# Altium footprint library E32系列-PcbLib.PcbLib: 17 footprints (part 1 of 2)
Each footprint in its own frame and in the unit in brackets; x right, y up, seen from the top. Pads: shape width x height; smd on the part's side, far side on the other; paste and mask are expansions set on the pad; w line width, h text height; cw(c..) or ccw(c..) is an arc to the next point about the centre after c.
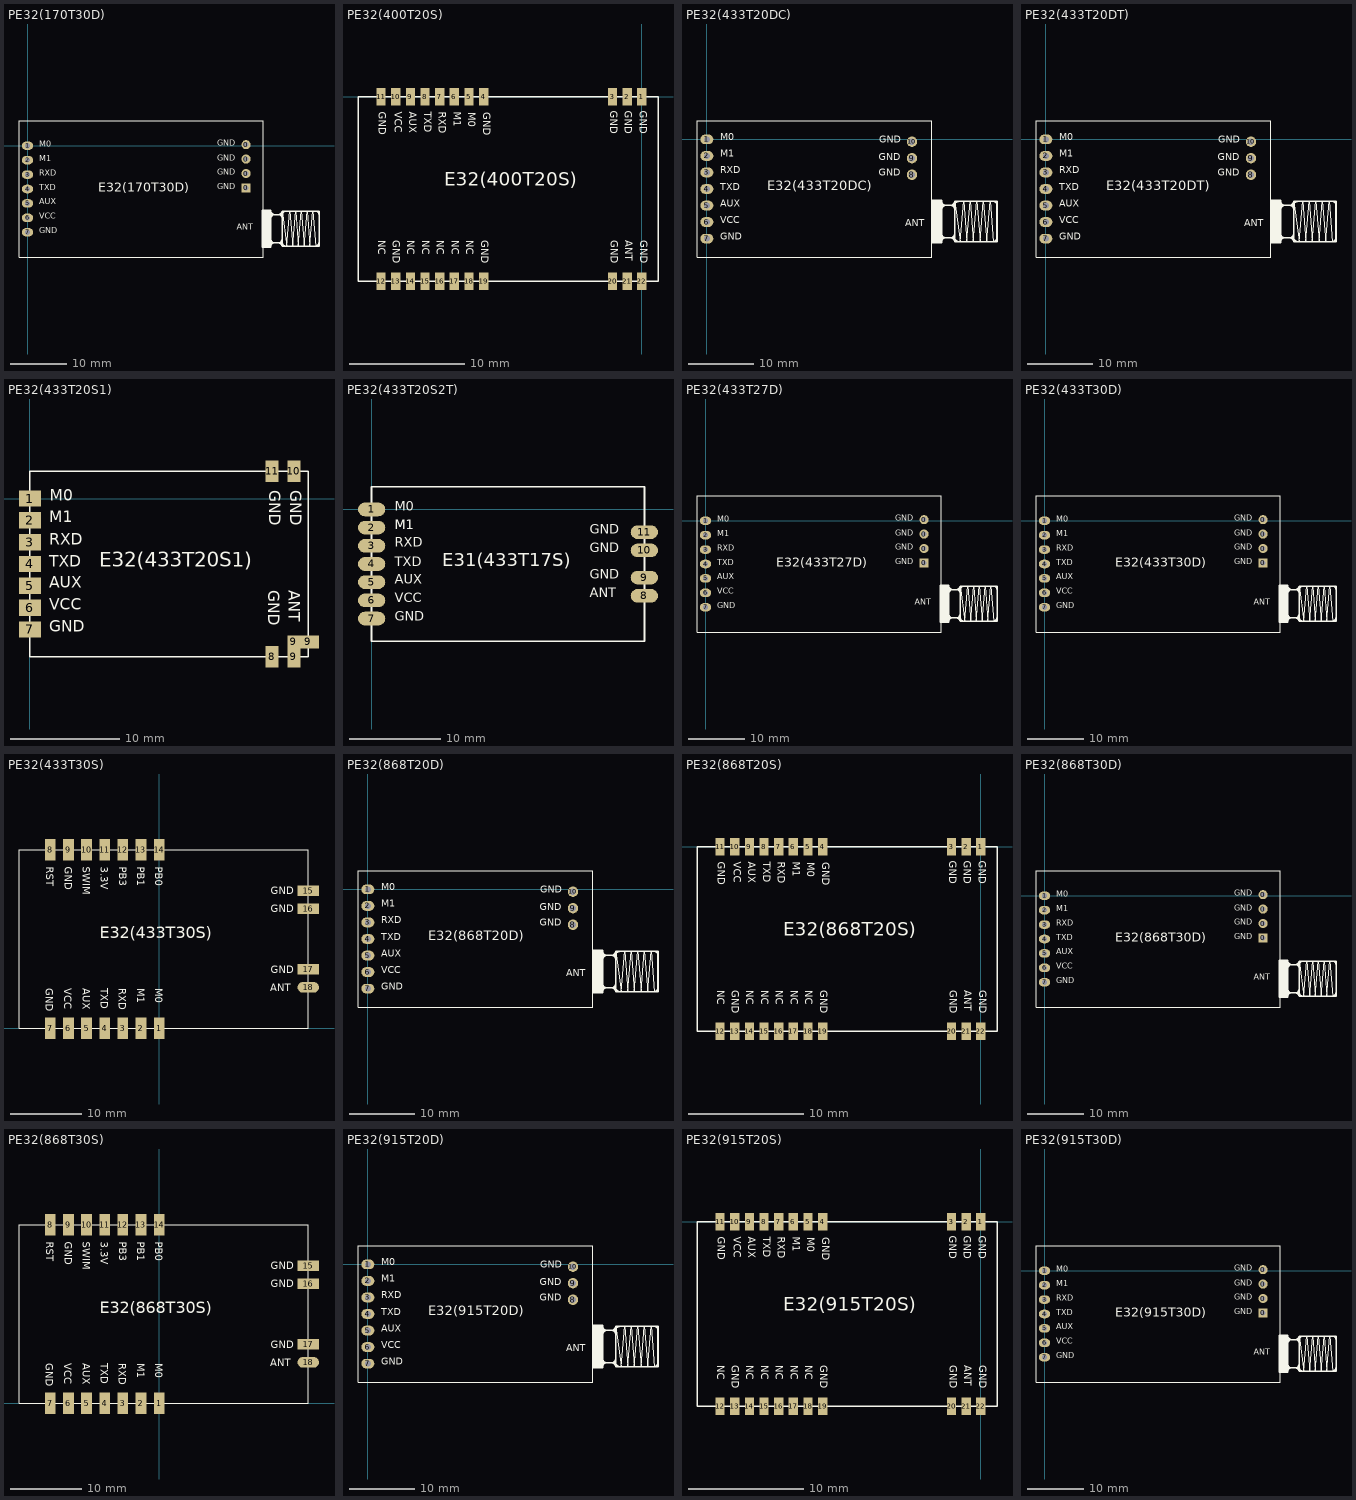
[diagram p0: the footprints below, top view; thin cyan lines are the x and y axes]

## PE32(170T30D) [mm] "43MM*24mm-D//SMA长度12.5mm"
pads (11):
  rect 1.6x1.6 hole 0.9: 0(38.5,-7.43)
  round 1.6 hole 0.9: 0(38.5,-4.89) 0(38.5,-2.35) 0(38.5,0.19)
  oval 2x1.5 hole 0.9: 1(0,0) 2(0,-2.54) 3(0,-5.08) 4(0,-7.62) 5(0,-10.16) 6(0,-12.7) 7(0,-15.24)
Top Overlay:
  rectangle: 41.35,-17.87 42.85,-11.37
  rectangle: 41.35,-17.865 42.85,-11.365
  lines w0.1: 45.7,-17.72 46.22,-11.52 ; 45.7,-17.72 44.85,-11.52 45.7,-17.72 ; 45.7,-17.72 46.22,-11.52 ; 46.22,-11.52 46.73,-17.72 ; 46.22,-11.52 46.73,-17.72 ; 46.73,-17.72 47.24,-11.52 ; 46.73,-17.72 47.24,-11.52 ; 47.24,-11.52 47.72,-17.72 ; 47.24,-11.52 47.72,-17.72 ; 47.72,-17.72 48.24,-11.52 ; 47.72,-17.72 48.24,-11.52 ; 48.24,-11.52 48.75,-17.72 ; 48.24,-11.52 48.75,-17.72 ; 48.75,-17.72 49.24,-11.52 ; 48.75,-17.72 49.24,-11.52 ; 49.24,-11.52 49.76,-17.72 ; 49.24,-11.52 49.76,-17.72 ; 49.76,-17.72 50.28,-11.52 ; 49.76,-17.72 50.28,-11.52 ; 50.28,-11.52 50.79,-17.72 50.28,-11.52 ; -1.5,-19.62 41.5,-19.62 41.5,4.38 -1.5,4.38 -1.5,-19.62
  lines w0.254: 41.35,-17.87 42.85,-17.87 ; 41.35,-17.87 41.35,-11.37 ; 41.35,-17.87 42.85,-17.87 ; 41.35,-17.87 41.35,-11.37 ; 41.35,-11.37 42.85,-11.37 ; 41.35,-11.37 42.85,-11.37 ; 42.85,-17.87 42.85,-11.37 ; 42.85,-17.87 42.85,-11.37 ; 42.85,-16.47 ccw(c43.5,-16.47) 43.5,-17.12 ; 42.85,-16.47 ccw(c43.5,-16.47) 43.5,-17.12 ; 42.85,-16.47 42.85,-16.1 42.85,-16.47 ; 42.85,-12.82 cw(c43.55,-12.82) 43.55,-12.12 ; 42.85,-12.82 cw(c43.55,-12.82) 43.55,-12.12 ; 42.85,-12.82 42.85,-13.74 42.85,-12.82 ; 42.85,-11.49 ccw(c43.48,-11.49) 43.48,-12.12 ; 42.85,-11.49 ccw(c43.48,-11.49) 43.48,-12.12 ; 42.85,-11.49 42.85,-11.37 ; 42.85,-11.49 42.85,-11.37 ; 43.4,-17.12 ccw(c43.4,-17.67) 42.85,-17.67 cw(c43.4,-17.67) 43.4,-17.12 ; 43.4,-17.12 44.25,-17.12 ; 43.4,-17.12 44.25,-17.12 ; 43.48,-12.12 44.25,-12.12 ; 43.48,-12.12 44.25,-12.12 ; 43.5,-17.12 44.22,-17.12 ; 43.5,-17.12 44.22,-17.12 ; 43.55,-12.12 44.25,-12.12 ; 43.55,-12.12 44.25,-12.12 ; 44.22,-17.12 ccw(c44.22,-16.49) 44.85,-16.49 cw(c44.22,-16.49) 44.22,-17.12 ; 44.25,-17.12 cw(c44.25,-17.72) 44.85,-17.72 ; 44.25,-17.12 cw(c44.25,-17.72) 44.85,-17.72 ; 44.25,-12.12 cw(c44.25,-12.72) 44.85,-12.72 ccw(c44.25,-12.72) 44.25,-12.12 ; 44.25,-12.12 ccw(c44.25,-11.52) 44.85,-11.52 ; 44.25,-12.12 ccw(c44.25,-11.52) 44.85,-11.52 ; 44.85,-17.72 44.85,-11.52 ; 44.85,-17.72 51.35,-17.72 ; 44.85,-17.72 44.85,-11.52 ; 44.85,-17.72 51.35,-17.72 ; 44.85,-11.52 51.35,-11.52 ; 44.85,-11.52 51.35,-11.52 ; 45.53,-17.72 cw(c45.53,-17.04) 44.85,-17.04 ccw(c45.53,-17.04) 45.53,-17.72 ; 45.53,-17.72 45.68,-17.72 45.53,-17.72 ; 50.73,-17.72 ccw(c50.73,-17.1) 51.35,-17.1 cw(c50.73,-17.1) 50.73,-17.72 ; 50.73,-17.72 50.5,-17.72 50.73,-17.72 ; 50.81,-11.52 cw(c50.81,-12.06) 51.35,-12.06 ccw(c50.81,-12.06) 50.81,-11.52 ; 50.81,-11.52 50.41,-11.52 50.81,-11.52 ; 51.35,-17.72 51.35,-11.52 ; 51.35,-17.72 51.35,-11.52 ; 42.68,-17.12 44.85,-17.12 42.68,-17.12 ; 42.85,-12.12 44.85,-12.12 42.85,-12.12 ; 44.85,-12.13 cw(c45.46,-12.13) 45.46,-11.52 ccw(c45.46,-12.13) 44.85,-12.13
  text "E32(170T30D)" at 12.446,-8.763 h2.8
  text "ANT" at 36.83,-15.19 h1.8
  text "M0" at 2.063,-0.54 h1.8
  text "M1" at 2.063,-3.08 h1.8
  text "RXD" at 2.063,-5.62 h1.8
  text "TXD" at 2.063,-8.16 h1.8
  text "AUX" at 2.063,-10.7 h1.8
  text "VCC" at 2.063,-13.24 h1.8
  text "GND" at 2.063,-15.78 h1.8
  text "GND" at 33.426,-5.429 h1.8
  text "GND" at 33.426,-3.016 h1.8
  text "GND" at 33.457,-0.381 h1.8
  text "GND" at 33.457,-8.001 h1.8

## PE32(400T20S) [mm] "26mm**16mm*3.23mm-S"
pads (22):
  rect 0.8x1.5 smd: 1(0,0) 2(-1.27,0) 3(-2.54,0) 4(-13.71,0) 5(-14.98,0) 6(-16.25,0) 7(-17.52,0) 8(-18.79,0) 9(-20.06,0) 10(-21.33,0) 11(-22.6,0) 12(-22.6,-16) 13(-21.33,-16) 14(-20.06,-16) 15(-18.79,-16) 16(-17.52,-16) 17(-16.25,-16) 18(-14.98,-16) 19(-13.71,-16) 20(-2.54,-16) 21(-1.27,-16) 22(0,-16)
Top Overlay:
  lines w0.127: -24.6,-16 1.4,-16 1.4,0 -24.6,0 -24.6,-16
  text "GND" at -1.687,-1.224 h1.1
  text "GND" at -2.966,-1.224 h1.1
  text "GND" at -2.916,-12.441 h1.1
  text "ANT" at -1.637,-12.441 h1.1
  text "GND" at -0.358,-12.441 h1.1
  text "GND" at -14.138,-12.441 h1.1
  text "NC" at -15.417,-12.441 h1.1
  text "NC" at -16.696,-12.441 h1.1
  text "NC" at -17.974,-12.441 h1.1
  text "NC" at -19.253,-12.441 h1.1
  text "NC" at -20.532,-12.441 h1.1
  text "GND" at -21.811,-12.441 h1.1
  text "NC" at -23.06,-12.441 h1.1
  text "GND" at -13.97,-1.351 h1.1
  text "GND" at -23.01,-1.301 h1.1
  text "VCC" at -21.651,-1.301 h1.1
  text "AUX" at -20.372,-1.301 h1.1
  text "TXD" at -19.093,-1.301 h1.1
  text "RXD" at -17.814,-1.301 h1.1
  text "M1" at -16.536,-1.301 h1.1
  text "M0" at -15.257,-1.351 h1.1
  text "E32(400T20S)" at -17.107,-8.126 h2
  text "GND" at -0.408,-1.224 h1.1

## PE32(433T20DC) [mm] "36mm*21mm-D/SMA长度12.5mm"
pads (10):
  oval 2x1.5 hole 0.9: 1(0,0) 2(0,-2.54) 3(0,-5.08) 4(0,-7.62) 5(0,-10.16) 6(0,-12.7) 7(0,-15.24)
  round 1.6 hole 1: 8(31.49,-5.43) 9(31.49,-2.89) 10(31.49,-0.35)
Top Overlay:
  rectangle: 34.54,-15.87 36.04,-9.37
  rectangle: 34.54,-15.865 36.04,-9.365
  lines w0.1: 38.89,-15.72 39.41,-9.52 ; 38.89,-15.72 38.04,-9.52 38.89,-15.72 ; 38.89,-15.72 39.41,-9.52 ; 39.41,-9.52 39.92,-15.72 ; 39.41,-9.52 39.92,-15.72 ; 39.92,-15.72 40.43,-9.52 ; 39.92,-15.72 40.43,-9.52 ; 40.43,-9.52 40.91,-15.72 ; 40.43,-9.52 40.91,-15.72 ; 40.91,-15.72 41.43,-9.52 ; 40.91,-15.72 41.43,-9.52 ; 41.43,-9.52 41.94,-15.72 ; 41.43,-9.52 41.94,-15.72 ; 41.94,-15.72 42.43,-9.52 ; 41.94,-15.72 42.43,-9.52 ; 42.43,-9.52 42.95,-15.72 ; 42.43,-9.52 42.95,-15.72 ; 42.95,-15.72 43.47,-9.52 ; 42.95,-15.72 43.47,-9.52 ; 43.47,-9.52 43.98,-15.72 43.47,-9.52 ; -1.51,-18.12 34.558,-18.12 34.558,2.88 -1.51,2.88 -1.51,-18.12
  lines w0.254: 34.54,-15.87 36.04,-15.87 ; 34.54,-15.87 34.54,-9.37 ; 34.54,-15.87 36.04,-15.87 ; 34.54,-15.87 34.54,-9.37 ; 34.54,-9.37 36.04,-9.37 ; 34.54,-9.37 36.04,-9.37 ; 36.04,-15.87 36.04,-9.37 ; 36.04,-15.87 36.04,-9.37 ; 36.04,-14.47 ccw(c36.69,-14.47) 36.69,-15.12 ; 36.04,-14.47 ccw(c36.69,-14.47) 36.69,-15.12 ; 36.04,-14.47 36.04,-14.1 36.04,-14.47 ; 36.04,-10.82 cw(c36.74,-10.82) 36.74,-10.12 ; 36.04,-10.82 cw(c36.74,-10.82) 36.74,-10.12 ; 36.04,-10.82 36.04,-11.74 36.04,-10.82 ; 36.04,-9.49 ccw(c36.67,-9.49) 36.67,-10.12 ; 36.04,-9.49 ccw(c36.67,-9.49) 36.67,-10.12 ; 36.04,-9.49 36.04,-9.37 ; 36.04,-9.49 36.04,-9.37 ; 36.59,-15.12 ccw(c36.59,-15.67) 36.04,-15.67 cw(c36.59,-15.67) 36.59,-15.12 ; 36.59,-15.12 37.44,-15.12 ; 36.59,-15.12 37.44,-15.12 ; 36.67,-10.12 37.44,-10.12 ; 36.67,-10.12 37.44,-10.12 ; 36.69,-15.12 37.41,-15.12 ; 36.69,-15.12 37.41,-15.12 ; 36.74,-10.12 37.44,-10.12 ; 36.74,-10.12 37.44,-10.12 ; 37.41,-15.12 ccw(c37.41,-14.49) 38.04,-14.49 cw(c37.41,-14.49) 37.41,-15.12 ; 37.44,-15.12 cw(c37.44,-15.72) 38.04,-15.72 ; 37.44,-15.12 cw(c37.44,-15.72) 38.04,-15.72 ; 37.44,-10.12 cw(c37.44,-10.72) 38.04,-10.72 ccw(c37.44,-10.72) 37.44,-10.12 ; 37.44,-10.12 ccw(c37.44,-9.52) 38.04,-9.52 ; 37.44,-10.12 ccw(c37.44,-9.52) 38.04,-9.52 ; 38.04,-15.72 38.04,-9.52 ; 38.04,-15.72 44.54,-15.72 ; 38.04,-15.72 38.04,-9.52 ; 38.04,-15.72 44.54,-15.72 ; 38.04,-9.52 44.54,-9.52 ; 38.04,-9.52 44.54,-9.52 ; 38.72,-15.72 cw(c38.72,-15.04) 38.04,-15.04 ccw(c38.72,-15.04) 38.72,-15.72 ; 38.72,-15.72 38.87,-15.72 38.72,-15.72 ; 43.92,-15.72 ccw(c43.92,-15.1) 44.54,-15.1 cw(c43.92,-15.1) 43.92,-15.72 ; 43.92,-15.72 43.69,-15.72 43.92,-15.72 ; 44,-9.52 cw(c44,-10.06) 44.54,-10.06 ccw(c44,-10.06) 44,-9.52 ; 44,-9.52 43.6,-9.52 44,-9.52 ; 44.54,-15.72 44.54,-9.52 ; 44.54,-15.72 44.54,-9.52 ; 35.87,-15.12 38.04,-15.12 35.87,-15.12 ; 36.04,-10.12 38.04,-10.12 36.04,-10.12 ; 38.04,-10.13 cw(c38.65,-10.13) 38.65,-9.52 ccw(c38.65,-10.13) 38.04,-10.13
  text "GND" at 2.063,-15.78 h1.8
  text "VCC" at 2.063,-13.24 h1.8
  text "AUX" at 2.063,-10.7 h1.8
  text "TXD" at 2.063,-8.16 h1.8
  text "RXD" at 2.063,-5.62 h1.8
  text "M1" at 2.063,-3.08 h1.8
  text "M0" at 2.063,-0.54 h1.8
  text "ANT" at 30.48,-13.716 h1.8
  text "GND" at 26.447,-0.921 h1.8
  text "GND" at 26.416,-3.556 h1.8
  text "GND" at 26.416,-5.969 h1.8
  text "E32(433T20DC)" at 9.271,-8.382 h2.5

## PE32(433T20DT) [mm] "36mm*21mm-D/SMA长度12.5mm"
pads (10):
  oval 2x1.5 hole 0.9: 1(0,0) 2(0,-2.54) 3(0,-5.08) 4(0,-7.62) 5(0,-10.16) 6(0,-12.7) 7(0,-15.24)
  round 1.6 hole 1: 8(31.49,-5.43) 9(31.49,-2.89) 10(31.49,-0.35)
Top Overlay:
  rectangle: 34.54,-15.87 36.04,-9.37
  rectangle: 34.54,-15.865 36.04,-9.365
  lines w0.1: 38.89,-15.72 39.41,-9.52 ; 38.89,-15.72 38.04,-9.52 38.89,-15.72 ; 38.89,-15.72 39.41,-9.52 ; 39.41,-9.52 39.92,-15.72 ; 39.41,-9.52 39.92,-15.72 ; 39.92,-15.72 40.43,-9.52 ; 39.92,-15.72 40.43,-9.52 ; 40.43,-9.52 40.91,-15.72 ; 40.43,-9.52 40.91,-15.72 ; 40.91,-15.72 41.43,-9.52 ; 40.91,-15.72 41.43,-9.52 ; 41.43,-9.52 41.94,-15.72 ; 41.43,-9.52 41.94,-15.72 ; 41.94,-15.72 42.43,-9.52 ; 41.94,-15.72 42.43,-9.52 ; 42.43,-9.52 42.95,-15.72 ; 42.43,-9.52 42.95,-15.72 ; 42.95,-15.72 43.47,-9.52 ; 42.95,-15.72 43.47,-9.52 ; 43.47,-9.52 43.98,-15.72 43.47,-9.52 ; -1.51,-18.12 34.558,-18.12 34.558,2.88 -1.51,2.88 -1.51,-18.12
  lines w0.254: 34.54,-15.87 36.04,-15.87 ; 34.54,-15.87 34.54,-9.37 ; 34.54,-15.87 36.04,-15.87 ; 34.54,-15.87 34.54,-9.37 ; 34.54,-9.37 36.04,-9.37 ; 34.54,-9.37 36.04,-9.37 ; 36.04,-15.87 36.04,-9.37 ; 36.04,-15.87 36.04,-9.37 ; 36.04,-14.47 ccw(c36.69,-14.47) 36.69,-15.12 ; 36.04,-14.47 ccw(c36.69,-14.47) 36.69,-15.12 ; 36.04,-14.47 36.04,-14.1 36.04,-14.47 ; 36.04,-10.82 cw(c36.74,-10.82) 36.74,-10.12 ; 36.04,-10.82 cw(c36.74,-10.82) 36.74,-10.12 ; 36.04,-10.82 36.04,-11.74 36.04,-10.82 ; 36.04,-9.49 ccw(c36.67,-9.49) 36.67,-10.12 ; 36.04,-9.49 ccw(c36.67,-9.49) 36.67,-10.12 ; 36.04,-9.49 36.04,-9.37 ; 36.04,-9.49 36.04,-9.37 ; 36.59,-15.12 ccw(c36.59,-15.67) 36.04,-15.67 cw(c36.59,-15.67) 36.59,-15.12 ; 36.59,-15.12 37.44,-15.12 ; 36.59,-15.12 37.44,-15.12 ; 36.67,-10.12 37.44,-10.12 ; 36.67,-10.12 37.44,-10.12 ; 36.69,-15.12 37.41,-15.12 ; 36.69,-15.12 37.41,-15.12 ; 36.74,-10.12 37.44,-10.12 ; 36.74,-10.12 37.44,-10.12 ; 37.41,-15.12 ccw(c37.41,-14.49) 38.04,-14.49 cw(c37.41,-14.49) 37.41,-15.12 ; 37.44,-15.12 cw(c37.44,-15.72) 38.04,-15.72 ; 37.44,-15.12 cw(c37.44,-15.72) 38.04,-15.72 ; 37.44,-10.12 cw(c37.44,-10.72) 38.04,-10.72 ccw(c37.44,-10.72) 37.44,-10.12 ; 37.44,-10.12 ccw(c37.44,-9.52) 38.04,-9.52 ; 37.44,-10.12 ccw(c37.44,-9.52) 38.04,-9.52 ; 38.04,-15.72 38.04,-9.52 ; 38.04,-15.72 44.54,-15.72 ; 38.04,-15.72 38.04,-9.52 ; 38.04,-15.72 44.54,-15.72 ; 38.04,-9.52 44.54,-9.52 ; 38.04,-9.52 44.54,-9.52 ; 38.72,-15.72 cw(c38.72,-15.04) 38.04,-15.04 ccw(c38.72,-15.04) 38.72,-15.72 ; 38.72,-15.72 38.87,-15.72 38.72,-15.72 ; 43.92,-15.72 ccw(c43.92,-15.1) 44.54,-15.1 cw(c43.92,-15.1) 43.92,-15.72 ; 43.92,-15.72 43.69,-15.72 43.92,-15.72 ; 44,-9.52 cw(c44,-10.06) 44.54,-10.06 ccw(c44,-10.06) 44,-9.52 ; 44,-9.52 43.6,-9.52 44,-9.52 ; 44.54,-15.72 44.54,-9.52 ; 44.54,-15.72 44.54,-9.52 ; 35.87,-15.12 38.04,-15.12 35.87,-15.12 ; 36.04,-10.12 38.04,-10.12 36.04,-10.12 ; 38.04,-10.13 cw(c38.65,-10.13) 38.65,-9.52 ccw(c38.65,-10.13) 38.04,-10.13
  text "GND" at 2.063,-15.78 h1.8
  text "VCC" at 2.063,-13.24 h1.8
  text "AUX" at 2.063,-10.7 h1.8
  text "TXD" at 2.063,-8.16 h1.8
  text "RXD" at 2.063,-5.62 h1.8
  text "M1" at 2.063,-3.08 h1.8
  text "M0" at 2.063,-0.54 h1.8
  text "ANT" at 30.48,-13.716 h1.8
  text "GND" at 26.447,-0.921 h1.8
  text "GND" at 26.416,-3.556 h1.8
  text "GND" at 26.416,-5.969 h1.8
  text "E32(433T20DT)" at 9.271,-8.382 h2.5

## PE32(433T20S1) [mm] "25.56mm*17mm*2.10mm-S"
pads (13):
  rect 2x1.5 smd: 1(0,0) 2(0,-2) 3(0,-4) 4(0,-6) 5(0,-8) 6(0,-10) 7(0,-12)
  rect 1.2x2 smd: 8(22.2,-14.5) 9(24.2,-14.5) 10(24.2,2.5) 11(22.2,2.5)
  rect 1.2x1.2 smd: 9(24.2,-13.14)
  rect 2x1.2 smd: 9(25.5,-13.14)
Top Overlay:
  lines w0.127: 0,-14.5 0,2.5 25.5,2.5 25.5,-14.5 0,-14.5
  text "ANT" at 23.368,-8.404 h1.8
  text "GND" at 21.463,-8.404 h1.8
  text "GND" at 23.495,0.74 h1.8
  text "GND" at 21.59,0.74 h1.8
  text "GND" at 1.778,-12.595 h1.8
  text "VCC" at 1.778,-10.563 h1.8
  text "AUX" at 1.778,-8.531 h1.8
  text "TXD" at 1.778,-6.626 h1.8
  text "RXD" at 1.778,-4.594 h1.8
  text "M1" at 1.778,-2.562 h1.8
  text "M0" at 1.809,-0.562 h1.8
  text "E32(433T20S1)" at 6.35,-6.731 h2.3

## PE32(433T20S2T) [mm] "30mm*17mm*2.4mm-S"
pads (11):
  oval 3x1.5 smd: 1(0,0) 2(0,-2) 3(0,-4) 4(0,-6) 5(0,-8) 6(0,-10) 7(0,-12) 8(30,-9.5) 9(30,-7.5) 10(30,-4.5) 11(30,-2.5)
Top Overlay:
  lines w0.2: 0,-14.5 30,-14.5 30,2.5 0,2.5 0,-14.5
  text "ANT" at 24.017,-10.064 h1.8
  text "GND" at 24.017,-8.032 h1.8
  text "GND" at 24.017,-5.111 h1.8
  text "GND" at 24.017,-3.079 h1.8
  text "GND" at 2.554,-12.604 h1.8
  text "VCC" at 2.554,-10.572 h1.8
  text "TXD" at 2.554,-6.635 h1.8
  text "RXD" at 2.554,-4.476 h1.8
  text "M1" at 2.554,-2.571 h1.8
  text "M1" at 2.554,-2.571 h1.8
  text "M0" at 2.554,-0.539 h1.8
  text "AUX" at 2.554,-8.54 h1.8
  text "E31(433T17S)" at 7.761,-6.762 h2.5

## PE32(433T27D) [mm] "43MM*24mm-D//SMA长度12.5mm"
pads (11):
  rect 1.6x1.6 hole 0.9: 0(38.5,-7.43)
  round 1.6 hole 0.9: 0(38.5,-4.89) 0(38.5,-2.35) 0(38.5,0.19)
  oval 2x1.5 hole 0.9: 1(0,0) 2(0,-2.54) 3(0,-5.08) 4(0,-7.62) 5(0,-10.16) 6(0,-12.7) 7(0,-15.24)
Top Overlay:
  rectangle: 41.35,-17.87 42.85,-11.37
  rectangle: 41.35,-17.865 42.85,-11.365
  lines w0.1: 45.7,-17.72 46.22,-11.52 ; 45.7,-17.72 44.85,-11.52 45.7,-17.72 ; 45.7,-17.72 46.22,-11.52 ; 46.22,-11.52 46.73,-17.72 ; 46.22,-11.52 46.73,-17.72 ; 46.73,-17.72 47.24,-11.52 ; 46.73,-17.72 47.24,-11.52 ; 47.24,-11.52 47.72,-17.72 ; 47.24,-11.52 47.72,-17.72 ; 47.72,-17.72 48.24,-11.52 ; 47.72,-17.72 48.24,-11.52 ; 48.24,-11.52 48.75,-17.72 ; 48.24,-11.52 48.75,-17.72 ; 48.75,-17.72 49.24,-11.52 ; 48.75,-17.72 49.24,-11.52 ; 49.24,-11.52 49.76,-17.72 ; 49.24,-11.52 49.76,-17.72 ; 49.76,-17.72 50.28,-11.52 ; 49.76,-17.72 50.28,-11.52 ; 50.28,-11.52 50.79,-17.72 50.28,-11.52 ; -1.5,-19.62 41.5,-19.62 41.5,4.38 -1.5,4.38 -1.5,-19.62
  lines w0.254: 41.35,-17.87 42.85,-17.87 ; 41.35,-17.87 41.35,-11.37 ; 41.35,-17.87 42.85,-17.87 ; 41.35,-17.87 41.35,-11.37 ; 41.35,-11.37 42.85,-11.37 ; 41.35,-11.37 42.85,-11.37 ; 42.85,-17.87 42.85,-11.37 ; 42.85,-17.87 42.85,-11.37 ; 42.85,-16.47 ccw(c43.5,-16.47) 43.5,-17.12 ; 42.85,-16.47 ccw(c43.5,-16.47) 43.5,-17.12 ; 42.85,-16.47 42.85,-16.1 42.85,-16.47 ; 42.85,-12.82 cw(c43.55,-12.82) 43.55,-12.12 ; 42.85,-12.82 cw(c43.55,-12.82) 43.55,-12.12 ; 42.85,-12.82 42.85,-13.74 42.85,-12.82 ; 42.85,-11.49 ccw(c43.48,-11.49) 43.48,-12.12 ; 42.85,-11.49 ccw(c43.48,-11.49) 43.48,-12.12 ; 42.85,-11.49 42.85,-11.37 ; 42.85,-11.49 42.85,-11.37 ; 43.4,-17.12 ccw(c43.4,-17.67) 42.85,-17.67 cw(c43.4,-17.67) 43.4,-17.12 ; 43.4,-17.12 44.25,-17.12 ; 43.4,-17.12 44.25,-17.12 ; 43.48,-12.12 44.25,-12.12 ; 43.48,-12.12 44.25,-12.12 ; 43.5,-17.12 44.22,-17.12 ; 43.5,-17.12 44.22,-17.12 ; 43.55,-12.12 44.25,-12.12 ; 43.55,-12.12 44.25,-12.12 ; 44.22,-17.12 ccw(c44.22,-16.49) 44.85,-16.49 cw(c44.22,-16.49) 44.22,-17.12 ; 44.25,-17.12 cw(c44.25,-17.72) 44.85,-17.72 ; 44.25,-17.12 cw(c44.25,-17.72) 44.85,-17.72 ; 44.25,-12.12 cw(c44.25,-12.72) 44.85,-12.72 ccw(c44.25,-12.72) 44.25,-12.12 ; 44.25,-12.12 ccw(c44.25,-11.52) 44.85,-11.52 ; 44.25,-12.12 ccw(c44.25,-11.52) 44.85,-11.52 ; 44.85,-17.72 44.85,-11.52 ; 44.85,-17.72 51.35,-17.72 ; 44.85,-17.72 44.85,-11.52 ; 44.85,-17.72 51.35,-17.72 ; 44.85,-11.52 51.35,-11.52 ; 44.85,-11.52 51.35,-11.52 ; 45.53,-17.72 cw(c45.53,-17.04) 44.85,-17.04 ccw(c45.53,-17.04) 45.53,-17.72 ; 45.53,-17.72 45.68,-17.72 45.53,-17.72 ; 50.73,-17.72 ccw(c50.73,-17.1) 51.35,-17.1 cw(c50.73,-17.1) 50.73,-17.72 ; 50.73,-17.72 50.5,-17.72 50.73,-17.72 ; 50.81,-11.52 cw(c50.81,-12.06) 51.35,-12.06 ccw(c50.81,-12.06) 50.81,-11.52 ; 50.81,-11.52 50.41,-11.52 50.81,-11.52 ; 51.35,-17.72 51.35,-11.52 ; 51.35,-17.72 51.35,-11.52 ; 42.68,-17.12 44.85,-17.12 42.68,-17.12 ; 42.85,-12.12 44.85,-12.12 42.85,-12.12 ; 44.85,-12.13 cw(c45.46,-12.13) 45.46,-11.52 ccw(c45.46,-12.13) 44.85,-12.13
  text "E32(433T27D)" at 12.446,-8.763 h2.8
  text "ANT" at 36.83,-15.19 h1.8
  text "M0" at 2.063,-0.54 h1.8
  text "M1" at 2.063,-3.08 h1.8
  text "RXD" at 2.063,-5.62 h1.8
  text "TXD" at 2.063,-8.16 h1.8
  text "AUX" at 2.063,-10.7 h1.8
  text "VCC" at 2.063,-13.24 h1.8
  text "GND" at 2.063,-15.78 h1.8
  text "GND" at 33.426,-5.429 h1.8
  text "GND" at 33.426,-3.016 h1.8
  text "GND" at 33.457,-0.381 h1.8
  text "GND" at 33.457,-8.001 h1.8

## PE32(433T30D) [mm] "43MM*24mm-D//SMA长度12.5mm"
pads (11):
  rect 1.6x1.6 hole 0.9: 0(38.5,-7.43)
  round 1.6 hole 0.9: 0(38.5,-4.89) 0(38.5,-2.35) 0(38.5,0.19)
  oval 2x1.5 hole 0.9: 1(0,0) 2(0,-2.54) 3(0,-5.08) 4(0,-7.62) 5(0,-10.16) 6(0,-12.7) 7(0,-15.24)
Top Overlay:
  rectangle: 41.35,-17.87 42.85,-11.37
  rectangle: 41.35,-17.865 42.85,-11.365
  lines w0.1: 45.7,-17.72 46.22,-11.52 ; 45.7,-17.72 44.85,-11.52 45.7,-17.72 ; 45.7,-17.72 46.22,-11.52 ; 46.22,-11.52 46.73,-17.72 ; 46.22,-11.52 46.73,-17.72 ; 46.73,-17.72 47.24,-11.52 ; 46.73,-17.72 47.24,-11.52 ; 47.24,-11.52 47.72,-17.72 ; 47.24,-11.52 47.72,-17.72 ; 47.72,-17.72 48.24,-11.52 ; 47.72,-17.72 48.24,-11.52 ; 48.24,-11.52 48.75,-17.72 ; 48.24,-11.52 48.75,-17.72 ; 48.75,-17.72 49.24,-11.52 ; 48.75,-17.72 49.24,-11.52 ; 49.24,-11.52 49.76,-17.72 ; 49.24,-11.52 49.76,-17.72 ; 49.76,-17.72 50.28,-11.52 ; 49.76,-17.72 50.28,-11.52 ; 50.28,-11.52 50.79,-17.72 50.28,-11.52 ; -1.5,-19.62 41.5,-19.62 41.5,4.38 -1.5,4.38 -1.5,-19.62
  lines w0.254: 41.35,-17.87 42.85,-17.87 ; 41.35,-17.87 41.35,-11.37 ; 41.35,-17.87 42.85,-17.87 ; 41.35,-17.87 41.35,-11.37 ; 41.35,-11.37 42.85,-11.37 ; 41.35,-11.37 42.85,-11.37 ; 42.85,-17.87 42.85,-11.37 ; 42.85,-17.87 42.85,-11.37 ; 42.85,-16.47 ccw(c43.5,-16.47) 43.5,-17.12 ; 42.85,-16.47 ccw(c43.5,-16.47) 43.5,-17.12 ; 42.85,-16.47 42.85,-16.1 42.85,-16.47 ; 42.85,-12.82 cw(c43.55,-12.82) 43.55,-12.12 ; 42.85,-12.82 cw(c43.55,-12.82) 43.55,-12.12 ; 42.85,-12.82 42.85,-13.74 42.85,-12.82 ; 42.85,-11.49 ccw(c43.48,-11.49) 43.48,-12.12 ; 42.85,-11.49 ccw(c43.48,-11.49) 43.48,-12.12 ; 42.85,-11.49 42.85,-11.37 ; 42.85,-11.49 42.85,-11.37 ; 43.4,-17.12 ccw(c43.4,-17.67) 42.85,-17.67 cw(c43.4,-17.67) 43.4,-17.12 ; 43.4,-17.12 44.25,-17.12 ; 43.4,-17.12 44.25,-17.12 ; 43.48,-12.12 44.25,-12.12 ; 43.48,-12.12 44.25,-12.12 ; 43.5,-17.12 44.22,-17.12 ; 43.5,-17.12 44.22,-17.12 ; 43.55,-12.12 44.25,-12.12 ; 43.55,-12.12 44.25,-12.12 ; 44.22,-17.12 ccw(c44.22,-16.49) 44.85,-16.49 cw(c44.22,-16.49) 44.22,-17.12 ; 44.25,-17.12 cw(c44.25,-17.72) 44.85,-17.72 ; 44.25,-17.12 cw(c44.25,-17.72) 44.85,-17.72 ; 44.25,-12.12 cw(c44.25,-12.72) 44.85,-12.72 ccw(c44.25,-12.72) 44.25,-12.12 ; 44.25,-12.12 ccw(c44.25,-11.52) 44.85,-11.52 ; 44.25,-12.12 ccw(c44.25,-11.52) 44.85,-11.52 ; 44.85,-17.72 44.85,-11.52 ; 44.85,-17.72 51.35,-17.72 ; 44.85,-17.72 44.85,-11.52 ; 44.85,-17.72 51.35,-17.72 ; 44.85,-11.52 51.35,-11.52 ; 44.85,-11.52 51.35,-11.52 ; 45.53,-17.72 cw(c45.53,-17.04) 44.85,-17.04 ccw(c45.53,-17.04) 45.53,-17.72 ; 45.53,-17.72 45.68,-17.72 45.53,-17.72 ; 50.73,-17.72 ccw(c50.73,-17.1) 51.35,-17.1 cw(c50.73,-17.1) 50.73,-17.72 ; 50.73,-17.72 50.5,-17.72 50.73,-17.72 ; 50.81,-11.52 cw(c50.81,-12.06) 51.35,-12.06 ccw(c50.81,-12.06) 50.81,-11.52 ; 50.81,-11.52 50.41,-11.52 50.81,-11.52 ; 51.35,-17.72 51.35,-11.52 ; 51.35,-17.72 51.35,-11.52 ; 42.68,-17.12 44.85,-17.12 42.68,-17.12 ; 42.85,-12.12 44.85,-12.12 42.85,-12.12 ; 44.85,-12.13 cw(c45.46,-12.13) 45.46,-11.52 ccw(c45.46,-12.13) 44.85,-12.13
  text "E32(433T30D)" at 12.446,-8.763 h2.8
  text "ANT" at 36.83,-15.19 h1.8
  text "M0" at 2.063,-0.54 h1.8
  text "M1" at 2.063,-3.08 h1.8
  text "RXD" at 2.063,-5.62 h1.8
  text "TXD" at 2.063,-8.16 h1.8
  text "AUX" at 2.063,-10.7 h1.8
  text "VCC" at 2.063,-13.24 h1.8
  text "GND" at 2.063,-15.78 h1.8
  text "GND" at 33.426,-5.429 h1.8
  text "GND" at 33.426,-3.016 h1.8
  text "GND" at 33.457,-0.381 h1.8
  text "GND" at 33.457,-8.001 h1.8

## PE32(433T30S) [mm] "40.5mm*25mm*3.80mm-S"
pads (18):
  rect 1.5x3 smd: 1(0,0) 2(-2.54,0) 3(-5.08,0) 4(-7.62,0) 5(-10.16,0) 6(-12.7,0) 7(-15.24,0) 8(-15.24,25) 9(-12.7,25) 10(-10.16,25) 11(-7.62,25) 12(-5.08,25) 13(-2.54,25) 14(0,25)
  rect 3x1.5 smd: 15(20.88,19.27) 16(20.88,16.73) 17(20.88,8.27)
  oval 3x1.5 smd: 18(20.88,5.73)
Top Overlay:
  lines w0.127: -19.62,0 20.88,0 20.88,25 -19.62,25 -19.62,0
  text "SWIM" at -10.73,22.606 h1
  text "GND" at 15.602,18.73 h1
  text "GND" at 15.602,16.22 h1
  text "PB0" at -0.557,22.592 h1
  text "PB1" at -3.067,22.592 h1
  text "PB3" at -5.617,22.592 h1
  text "3.3V" at -8.147,22.592 h1
  text "GND" at -13.237,22.592 h1
  text "RST" at -15.827,22.592 h1
  text "GND" at -15.847,5.575 h1
  text "VCC" at -13.257,5.575 h1
  text "AUX" at -10.707,5.575 h1
  text "TXD" at -8.167,5.575 h1
  text "RXD" at -5.637,5.575 h1
  text "M1" at -3.087,5.575 h1
  text "M0" at -0.577,5.575 h1
  text "ANT" at 15.554,5.17 h1
  text "GND" at 15.602,7.72 h1
  text "E32(433T30S)" at -8.317,12.065 h2.8

## PE32(868T20D) [mm] "36mm*21mm-D/SMA长度12.5mm"
pads (10):
  oval 2x1.5 hole 0.9: 1(0,0) 2(0,-2.54) 3(0,-5.08) 4(0,-7.62) 5(0,-10.16) 6(0,-12.7) 7(0,-15.24)
  round 1.6 hole 1: 8(31.49,-5.43) 9(31.49,-2.89) 10(31.49,-0.35)
Top Overlay:
  rectangle: 34.54,-15.87 36.04,-9.37
  rectangle: 34.54,-15.865 36.04,-9.365
  lines w0.1: 38.89,-15.72 39.41,-9.52 ; 38.89,-15.72 38.04,-9.52 38.89,-15.72 ; 38.89,-15.72 39.41,-9.52 ; 39.41,-9.52 39.92,-15.72 ; 39.41,-9.52 39.92,-15.72 ; 39.92,-15.72 40.43,-9.52 ; 39.92,-15.72 40.43,-9.52 ; 40.43,-9.52 40.91,-15.72 ; 40.43,-9.52 40.91,-15.72 ; 40.91,-15.72 41.43,-9.52 ; 40.91,-15.72 41.43,-9.52 ; 41.43,-9.52 41.94,-15.72 ; 41.43,-9.52 41.94,-15.72 ; 41.94,-15.72 42.43,-9.52 ; 41.94,-15.72 42.43,-9.52 ; 42.43,-9.52 42.95,-15.72 ; 42.43,-9.52 42.95,-15.72 ; 42.95,-15.72 43.47,-9.52 ; 42.95,-15.72 43.47,-9.52 ; 43.47,-9.52 43.98,-15.72 43.47,-9.52 ; -1.51,-18.12 34.558,-18.12 34.558,2.88 -1.51,2.88 -1.51,-18.12
  lines w0.254: 34.54,-15.87 36.04,-15.87 ; 34.54,-15.87 34.54,-9.37 ; 34.54,-15.87 36.04,-15.87 ; 34.54,-15.87 34.54,-9.37 ; 34.54,-9.37 36.04,-9.37 ; 34.54,-9.37 36.04,-9.37 ; 36.04,-15.87 36.04,-9.37 ; 36.04,-15.87 36.04,-9.37 ; 36.04,-14.47 ccw(c36.69,-14.47) 36.69,-15.12 ; 36.04,-14.47 ccw(c36.69,-14.47) 36.69,-15.12 ; 36.04,-14.47 36.04,-14.1 36.04,-14.47 ; 36.04,-10.82 cw(c36.74,-10.82) 36.74,-10.12 ; 36.04,-10.82 cw(c36.74,-10.82) 36.74,-10.12 ; 36.04,-10.82 36.04,-11.74 36.04,-10.82 ; 36.04,-9.49 ccw(c36.67,-9.49) 36.67,-10.12 ; 36.04,-9.49 ccw(c36.67,-9.49) 36.67,-10.12 ; 36.04,-9.49 36.04,-9.37 ; 36.04,-9.49 36.04,-9.37 ; 36.59,-15.12 ccw(c36.59,-15.67) 36.04,-15.67 cw(c36.59,-15.67) 36.59,-15.12 ; 36.59,-15.12 37.44,-15.12 ; 36.59,-15.12 37.44,-15.12 ; 36.67,-10.12 37.44,-10.12 ; 36.67,-10.12 37.44,-10.12 ; 36.69,-15.12 37.41,-15.12 ; 36.69,-15.12 37.41,-15.12 ; 36.74,-10.12 37.44,-10.12 ; 36.74,-10.12 37.44,-10.12 ; 37.41,-15.12 ccw(c37.41,-14.49) 38.04,-14.49 cw(c37.41,-14.49) 37.41,-15.12 ; 37.44,-15.12 cw(c37.44,-15.72) 38.04,-15.72 ; 37.44,-15.12 cw(c37.44,-15.72) 38.04,-15.72 ; 37.44,-10.12 cw(c37.44,-10.72) 38.04,-10.72 ccw(c37.44,-10.72) 37.44,-10.12 ; 37.44,-10.12 ccw(c37.44,-9.52) 38.04,-9.52 ; 37.44,-10.12 ccw(c37.44,-9.52) 38.04,-9.52 ; 38.04,-15.72 38.04,-9.52 ; 38.04,-15.72 44.54,-15.72 ; 38.04,-15.72 38.04,-9.52 ; 38.04,-15.72 44.54,-15.72 ; 38.04,-9.52 44.54,-9.52 ; 38.04,-9.52 44.54,-9.52 ; 38.72,-15.72 cw(c38.72,-15.04) 38.04,-15.04 ccw(c38.72,-15.04) 38.72,-15.72 ; 38.72,-15.72 38.87,-15.72 38.72,-15.72 ; 43.92,-15.72 ccw(c43.92,-15.1) 44.54,-15.1 cw(c43.92,-15.1) 43.92,-15.72 ; 43.92,-15.72 43.69,-15.72 43.92,-15.72 ; 44,-9.52 cw(c44,-10.06) 44.54,-10.06 ccw(c44,-10.06) 44,-9.52 ; 44,-9.52 43.6,-9.52 44,-9.52 ; 44.54,-15.72 44.54,-9.52 ; 44.54,-15.72 44.54,-9.52 ; 35.87,-15.12 38.04,-15.12 35.87,-15.12 ; 36.04,-10.12 38.04,-10.12 36.04,-10.12 ; 38.04,-10.13 cw(c38.65,-10.13) 38.65,-9.52 ccw(c38.65,-10.13) 38.04,-10.13
  text "GND" at 2.063,-15.78 h1.8
  text "VCC" at 2.063,-13.24 h1.8
  text "AUX" at 2.063,-10.7 h1.8
  text "TXD" at 2.063,-8.16 h1.8
  text "RXD" at 2.063,-5.62 h1.8
  text "M1" at 2.063,-3.08 h1.8
  text "M0" at 2.063,-0.54 h1.8
  text "ANT" at 30.48,-13.716 h1.8
  text "GND" at 26.447,-0.921 h1.8
  text "GND" at 26.416,-3.556 h1.8
  text "GND" at 26.416,-5.969 h1.8
  text "E32(868T20D)" at 9.271,-8.382 h2.5

## PE32(868T20S) [mm] "26mm**16mm*3.23mm-S"
pads (22):
  rect 0.8x1.5 smd: 1(0,0) 2(-1.27,0) 3(-2.54,0) 4(-13.71,0) 5(-14.98,0) 6(-16.25,0) 7(-17.52,0) 8(-18.79,0) 9(-20.06,0) 10(-21.33,0) 11(-22.6,0) 12(-22.6,-16) 13(-21.33,-16) 14(-20.06,-16) 15(-18.79,-16) 16(-17.52,-16) 17(-16.25,-16) 18(-14.98,-16) 19(-13.71,-16) 20(-2.54,-16) 21(-1.27,-16) 22(0,-16)
Top Overlay:
  lines w0.127: -24.6,-16 1.4,-16 1.4,0 -24.6,0 -24.6,-16
  text "GND" at -1.687,-1.224 h1.1
  text "GND" at -2.966,-1.224 h1.1
  text "GND" at -2.916,-12.441 h1.1
  text "ANT" at -1.637,-12.441 h1.1
  text "GND" at -0.358,-12.441 h1.1
  text "GND" at -14.138,-12.441 h1.1
  text "NC" at -15.417,-12.441 h1.1
  text "NC" at -16.696,-12.441 h1.1
  text "NC" at -17.974,-12.441 h1.1
  text "NC" at -19.253,-12.441 h1.1
  text "NC" at -20.532,-12.441 h1.1
  text "GND" at -21.811,-12.441 h1.1
  text "NC" at -23.06,-12.441 h1.1
  text "GND" at -13.97,-1.351 h1.1
  text "GND" at -23.01,-1.301 h1.1
  text "VCC" at -21.651,-1.301 h1.1
  text "AUX" at -20.372,-1.301 h1.1
  text "TXD" at -19.093,-1.301 h1.1
  text "RXD" at -17.814,-1.301 h1.1
  text "M1" at -16.536,-1.301 h1.1
  text "M0" at -15.257,-1.351 h1.1
  text "E32(868T20S)" at -17.107,-8.126 h2
  text "GND" at -0.408,-1.224 h1.1

## PE32(868T30D) [mm] "43MM*24mm-D//SMA长度12.5mm"
pads (11):
  rect 1.6x1.6 hole 0.9: 0(38.5,-7.43)
  round 1.6 hole 0.9: 0(38.5,-4.89) 0(38.5,-2.35) 0(38.5,0.19)
  oval 2x1.5 hole 0.9: 1(0,0) 2(0,-2.54) 3(0,-5.08) 4(0,-7.62) 5(0,-10.16) 6(0,-12.7) 7(0,-15.24)
Top Overlay:
  rectangle: 41.35,-17.865 42.85,-11.365
  rectangle: 41.35,-17.87 42.85,-11.37
  lines w0.1: 45.7,-17.72 44.85,-11.52 45.7,-17.72 ; 45.7,-17.72 46.22,-11.52 ; 45.7,-17.72 46.22,-11.52 ; 46.22,-11.52 46.73,-17.72 ; 46.22,-11.52 46.73,-17.72 ; 46.73,-17.72 47.24,-11.52 ; 46.73,-17.72 47.24,-11.52 ; 47.24,-11.52 47.72,-17.72 ; 47.24,-11.52 47.72,-17.72 ; 47.72,-17.72 48.24,-11.52 ; 47.72,-17.72 48.24,-11.52 ; 48.24,-11.52 48.75,-17.72 ; 48.24,-11.52 48.75,-17.72 ; 48.75,-17.72 49.24,-11.52 ; 48.75,-17.72 49.24,-11.52 ; 49.24,-11.52 49.76,-17.72 ; 49.24,-11.52 49.76,-17.72 ; 49.76,-17.72 50.28,-11.52 ; 49.76,-17.72 50.28,-11.52 ; 50.28,-11.52 50.79,-17.72 50.28,-11.52 ; -1.5,-19.62 -1.5,4.38 41.5,4.38 41.5,-19.62 -1.5,-19.62
  lines w0.254: 41.35,-17.87 41.35,-11.37 ; 41.35,-17.87 42.85,-17.87 ; 41.35,-17.87 41.35,-11.37 ; 41.35,-17.87 42.85,-17.87 ; 41.35,-11.37 42.85,-11.37 ; 41.35,-11.37 42.85,-11.37 ; 42.85,-17.87 42.85,-11.37 ; 42.85,-17.87 42.85,-11.37 ; 42.85,-16.47 ccw(c43.5,-16.47) 43.5,-17.12 ; 42.85,-16.47 ccw(c43.5,-16.47) 43.5,-17.12 ; 42.85,-16.47 42.85,-16.1 42.85,-16.47 ; 42.85,-12.82 cw(c43.55,-12.82) 43.55,-12.12 ; 42.85,-12.82 cw(c43.55,-12.82) 43.55,-12.12 ; 42.85,-12.82 42.85,-13.74 42.85,-12.82 ; 42.85,-11.49 ccw(c43.48,-11.49) 43.48,-12.12 ; 42.85,-11.49 ccw(c43.48,-11.49) 43.48,-12.12 ; 42.85,-11.49 42.85,-11.37 ; 42.85,-11.49 42.85,-11.37 ; 43.4,-17.12 ccw(c43.4,-17.67) 42.85,-17.67 cw(c43.4,-17.67) 43.4,-17.12 ; 43.4,-17.12 44.25,-17.12 ; 43.4,-17.12 44.25,-17.12 ; 43.48,-12.12 44.25,-12.12 ; 43.48,-12.12 44.25,-12.12 ; 43.5,-17.12 44.22,-17.12 ; 43.5,-17.12 44.22,-17.12 ; 43.55,-12.12 44.25,-12.12 ; 43.55,-12.12 44.25,-12.12 ; 44.22,-17.12 ccw(c44.22,-16.49) 44.85,-16.49 cw(c44.22,-16.49) 44.22,-17.12 ; 44.25,-17.12 cw(c44.25,-17.72) 44.85,-17.72 ; 44.25,-17.12 cw(c44.25,-17.72) 44.85,-17.72 ; 44.25,-12.12 ccw(c44.25,-11.52) 44.85,-11.52 ; 44.25,-12.12 cw(c44.25,-12.72) 44.85,-12.72 ccw(c44.25,-12.72) 44.25,-12.12 ; 44.25,-12.12 ccw(c44.25,-11.52) 44.85,-11.52 ; 44.85,-17.72 51.35,-17.72 ; 44.85,-17.72 44.85,-11.52 ; 44.85,-17.72 51.35,-17.72 ; 44.85,-17.72 44.85,-11.52 ; 44.85,-11.52 51.35,-11.52 ; 44.85,-11.52 51.35,-11.52 ; 45.53,-17.72 cw(c45.53,-17.04) 44.85,-17.04 ccw(c45.53,-17.04) 45.53,-17.72 ; 45.53,-17.72 45.68,-17.72 45.53,-17.72 ; 50.73,-17.72 ccw(c50.73,-17.1) 51.35,-17.1 cw(c50.73,-17.1) 50.73,-17.72 ; 50.73,-17.72 50.5,-17.72 50.73,-17.72 ; 50.81,-11.52 cw(c50.81,-12.06) 51.35,-12.06 ccw(c50.81,-12.06) 50.81,-11.52 ; 50.81,-11.52 50.41,-11.52 50.81,-11.52 ; 51.35,-17.72 51.35,-11.52 ; 51.35,-17.72 51.35,-11.52 ; 42.68,-17.12 44.85,-17.12 42.68,-17.12 ; 42.85,-12.12 44.85,-12.12 42.85,-12.12 ; 44.85,-12.13 cw(c45.46,-12.13) 45.46,-11.52 ccw(c45.46,-12.13) 44.85,-12.13
  text "GND" at 33.457,-8.001 h1.8
  text "GND" at 33.457,-0.381 h1.8
  text "GND" at 33.426,-3.016 h1.8
  text "GND" at 33.426,-5.429 h1.8
  text "GND" at 2.063,-15.78 h1.8
  text "VCC" at 2.063,-13.24 h1.8
  text "AUX" at 2.063,-10.7 h1.8
  text "TXD" at 2.063,-8.16 h1.8
  text "RXD" at 2.063,-5.62 h1.8
  text "M1" at 2.063,-3.08 h1.8
  text "M0" at 2.063,-0.54 h1.8
  text "ANT" at 36.83,-15.19 h1.8
  text "E32(868T30D)" at 12.446,-8.763 h2.8

## PE32(868T30S) [mm] "40.5mm*25mm*3.80mm-S"
pads (18):
  rect 1.5x3 smd: 1(0,0) 2(-2.54,0) 3(-5.08,0) 4(-7.62,0) 5(-10.16,0) 6(-12.7,0) 7(-15.24,0) 8(-15.24,25) 9(-12.7,25) 10(-10.16,25) 11(-7.62,25) 12(-5.08,25) 13(-2.54,25) 14(0,25)
  rect 3x1.5 smd: 15(20.88,19.27) 16(20.88,16.73) 17(20.88,8.27)
  oval 3x1.5 smd: 18(20.88,5.73)
Top Overlay:
  lines w0.127: -19.62,0 20.88,0 20.88,25 -19.62,25 -19.62,0
  text "SWIM" at -10.73,22.606 h1
  text "GND" at 15.602,18.73 h1
  text "GND" at 15.602,16.22 h1
  text "PB0" at -0.557,22.592 h1
  text "PB1" at -3.067,22.592 h1
  text "PB3" at -5.617,22.592 h1
  text "3.3V" at -8.147,22.592 h1
  text "GND" at -13.237,22.592 h1
  text "RST" at -15.827,22.592 h1
  text "GND" at -15.847,5.575 h1
  text "VCC" at -13.257,5.575 h1
  text "AUX" at -10.707,5.575 h1
  text "TXD" at -8.167,5.575 h1
  text "RXD" at -5.637,5.575 h1
  text "M1" at -3.087,5.575 h1
  text "M0" at -0.577,5.575 h1
  text "ANT" at 15.554,5.17 h1
  text "GND" at 15.602,7.72 h1
  text "E32(868T30S)" at -8.317,12.065 h2.8

## PE32(915T20D) [mm] "36mm*21mm-D/SMA长度12.5mm"
pads (10):
  oval 2x1.5 hole 0.9: 1(0,0) 2(0,-2.54) 3(0,-5.08) 4(0,-7.62) 5(0,-10.16) 6(0,-12.7) 7(0,-15.24)
  round 1.6 hole 1: 8(31.49,-5.43) 9(31.49,-2.89) 10(31.49,-0.35)
Top Overlay:
  rectangle: 34.54,-15.865 36.04,-9.365
  rectangle: 34.54,-15.87 36.04,-9.37
  lines w0.1: 38.89,-15.72 38.04,-9.52 38.89,-15.72 ; 38.89,-15.72 39.41,-9.52 ; 38.89,-15.72 39.41,-9.52 ; 39.41,-9.52 39.92,-15.72 ; 39.41,-9.52 39.92,-15.72 ; 39.92,-15.72 40.43,-9.52 ; 39.92,-15.72 40.43,-9.52 ; 40.43,-9.52 40.91,-15.72 ; 40.43,-9.52 40.91,-15.72 ; 40.91,-15.72 41.43,-9.52 ; 40.91,-15.72 41.43,-9.52 ; 41.43,-9.52 41.94,-15.72 ; 41.43,-9.52 41.94,-15.72 ; 41.94,-15.72 42.43,-9.52 ; 41.94,-15.72 42.43,-9.52 ; 42.43,-9.52 42.95,-15.72 ; 42.43,-9.52 42.95,-15.72 ; 42.95,-15.72 43.47,-9.52 ; 42.95,-15.72 43.47,-9.52 ; 43.47,-9.52 43.98,-15.72 43.47,-9.52 ; -1.51,-18.12 -1.51,2.88 34.558,2.88 34.558,-18.12 -1.51,-18.12
  lines w0.254: 34.54,-15.87 34.54,-9.37 ; 34.54,-15.87 36.04,-15.87 ; 34.54,-15.87 34.54,-9.37 ; 34.54,-15.87 36.04,-15.87 ; 34.54,-9.37 36.04,-9.37 ; 34.54,-9.37 36.04,-9.37 ; 36.04,-15.87 36.04,-9.37 ; 36.04,-15.87 36.04,-9.37 ; 36.04,-14.47 ccw(c36.69,-14.47) 36.69,-15.12 ; 36.04,-14.47 ccw(c36.69,-14.47) 36.69,-15.12 ; 36.04,-14.47 36.04,-14.1 36.04,-14.47 ; 36.04,-10.82 cw(c36.74,-10.82) 36.74,-10.12 ; 36.04,-10.82 cw(c36.74,-10.82) 36.74,-10.12 ; 36.04,-10.82 36.04,-11.74 36.04,-10.82 ; 36.04,-9.49 ccw(c36.67,-9.49) 36.67,-10.12 ; 36.04,-9.49 ccw(c36.67,-9.49) 36.67,-10.12 ; 36.04,-9.49 36.04,-9.37 ; 36.04,-9.49 36.04,-9.37 ; 36.59,-15.12 ccw(c36.59,-15.67) 36.04,-15.67 cw(c36.59,-15.67) 36.59,-15.12 ; 36.59,-15.12 37.44,-15.12 ; 36.59,-15.12 37.44,-15.12 ; 36.67,-10.12 37.44,-10.12 ; 36.67,-10.12 37.44,-10.12 ; 36.69,-15.12 37.41,-15.12 ; 36.69,-15.12 37.41,-15.12 ; 36.74,-10.12 37.44,-10.12 ; 36.74,-10.12 37.44,-10.12 ; 37.41,-15.12 ccw(c37.41,-14.49) 38.04,-14.49 cw(c37.41,-14.49) 37.41,-15.12 ; 37.44,-15.12 cw(c37.44,-15.72) 38.04,-15.72 ; 37.44,-15.12 cw(c37.44,-15.72) 38.04,-15.72 ; 37.44,-10.12 ccw(c37.44,-9.52) 38.04,-9.52 ; 37.44,-10.12 cw(c37.44,-10.72) 38.04,-10.72 ccw(c37.44,-10.72) 37.44,-10.12 ; 37.44,-10.12 ccw(c37.44,-9.52) 38.04,-9.52 ; 38.04,-15.72 44.54,-15.72 ; 38.04,-15.72 38.04,-9.52 ; 38.04,-15.72 44.54,-15.72 ; 38.04,-15.72 38.04,-9.52 ; 38.04,-9.52 44.54,-9.52 ; 38.04,-9.52 44.54,-9.52 ; 38.72,-15.72 cw(c38.72,-15.04) 38.04,-15.04 ccw(c38.72,-15.04) 38.72,-15.72 ; 38.72,-15.72 38.87,-15.72 38.72,-15.72 ; 43.92,-15.72 ccw(c43.92,-15.1) 44.54,-15.1 cw(c43.92,-15.1) 43.92,-15.72 ; 43.92,-15.72 43.69,-15.72 43.92,-15.72 ; 44,-9.52 cw(c44,-10.06) 44.54,-10.06 ccw(c44,-10.06) 44,-9.52 ; 44,-9.52 43.6,-9.52 44,-9.52 ; 44.54,-15.72 44.54,-9.52 ; 44.54,-15.72 44.54,-9.52 ; 35.87,-15.12 38.04,-15.12 35.87,-15.12 ; 36.04,-10.12 38.04,-10.12 36.04,-10.12 ; 38.04,-10.13 cw(c38.65,-10.13) 38.65,-9.52 ccw(c38.65,-10.13) 38.04,-10.13
  text "E32(915T20D)" at 9.271,-8.382 h2.5
  text "GND" at 26.416,-5.969 h1.8
  text "GND" at 26.416,-3.556 h1.8
  text "GND" at 26.447,-0.921 h1.8
  text "ANT" at 30.48,-13.716 h1.8
  text "M0" at 2.063,-0.54 h1.8
  text "M1" at 2.063,-3.08 h1.8
  text "RXD" at 2.063,-5.62 h1.8
  text "TXD" at 2.063,-8.16 h1.8
  text "AUX" at 2.063,-10.7 h1.8
  text "VCC" at 2.063,-13.24 h1.8
  text "GND" at 2.063,-15.78 h1.8

## PE32(915T20S) [mm] "26mm**16mm*3.23mm-S"
pads (22):
  rect 0.8x1.5 smd: 1(0,0) 2(-1.27,0) 3(-2.54,0) 4(-13.71,0) 5(-14.98,0) 6(-16.25,0) 7(-17.52,0) 8(-18.79,0) 9(-20.06,0) 10(-21.33,0) 11(-22.6,0) 12(-22.6,-16) 13(-21.33,-16) 14(-20.06,-16) 15(-18.79,-16) 16(-17.52,-16) 17(-16.25,-16) 18(-14.98,-16) 19(-13.71,-16) 20(-2.54,-16) 21(-1.27,-16) 22(0,-16)
Top Overlay:
  lines w0.127: -24.6,-16 1.4,-16 1.4,0 -24.6,0 -24.6,-16
  text "GND" at -1.687,-1.224 h1.1
  text "GND" at -2.966,-1.224 h1.1
  text "GND" at -2.916,-12.441 h1.1
  text "ANT" at -1.637,-12.441 h1.1
  text "GND" at -0.358,-12.441 h1.1
  text "GND" at -14.138,-12.441 h1.1
  text "NC" at -15.417,-12.441 h1.1
  text "NC" at -16.696,-12.441 h1.1
  text "NC" at -17.974,-12.441 h1.1
  text "NC" at -19.253,-12.441 h1.1
  text "NC" at -20.532,-12.441 h1.1
  text "GND" at -21.811,-12.441 h1.1
  text "NC" at -23.06,-12.441 h1.1
  text "GND" at -13.97,-1.351 h1.1
  text "GND" at -23.01,-1.301 h1.1
  text "VCC" at -21.651,-1.301 h1.1
  text "AUX" at -20.372,-1.301 h1.1
  text "TXD" at -19.093,-1.301 h1.1
  text "RXD" at -17.814,-1.301 h1.1
  text "M1" at -16.536,-1.301 h1.1
  text "M0" at -15.257,-1.351 h1.1
  text "E32(915T20S)" at -17.107,-8.126 h2
  text "GND" at -0.408,-1.224 h1.1

## PE32(915T30D) [mm] "43MM*24mm-D//SMA长度12.5mm"
pads (11):
  rect 1.6x1.6 hole 0.9: 0(38.5,-7.43)
  round 1.6 hole 0.9: 0(38.5,-4.89) 0(38.5,-2.35) 0(38.5,0.19)
  oval 2x1.5 hole 0.9: 1(0,0) 2(0,-2.54) 3(0,-5.08) 4(0,-7.62) 5(0,-10.16) 6(0,-12.7) 7(0,-15.24)
Top Overlay:
  rectangle: 41.35,-17.87 42.85,-11.37
  rectangle: 41.35,-17.865 42.85,-11.365
  lines w0.1: 45.7,-17.72 46.22,-11.52 ; 45.7,-17.72 44.85,-11.52 45.7,-17.72 ; 45.7,-17.72 46.22,-11.52 ; 46.22,-11.52 46.73,-17.72 ; 46.22,-11.52 46.73,-17.72 ; 46.73,-17.72 47.24,-11.52 ; 46.73,-17.72 47.24,-11.52 ; 47.24,-11.52 47.72,-17.72 ; 47.24,-11.52 47.72,-17.72 ; 47.72,-17.72 48.24,-11.52 ; 47.72,-17.72 48.24,-11.52 ; 48.24,-11.52 48.75,-17.72 ; 48.24,-11.52 48.75,-17.72 ; 48.75,-17.72 49.24,-11.52 ; 48.75,-17.72 49.24,-11.52 ; 49.24,-11.52 49.76,-17.72 ; 49.24,-11.52 49.76,-17.72 ; 49.76,-17.72 50.28,-11.52 ; 49.76,-17.72 50.28,-11.52 ; 50.28,-11.52 50.79,-17.72 50.28,-11.52 ; -1.5,-19.62 41.5,-19.62 41.5,4.38 -1.5,4.38 -1.5,-19.62
  lines w0.254: 41.35,-17.87 42.85,-17.87 ; 41.35,-17.87 41.35,-11.37 ; 41.35,-17.87 42.85,-17.87 ; 41.35,-17.87 41.35,-11.37 ; 41.35,-11.37 42.85,-11.37 ; 41.35,-11.37 42.85,-11.37 ; 42.85,-17.87 42.85,-11.37 ; 42.85,-17.87 42.85,-11.37 ; 42.85,-16.47 ccw(c43.5,-16.47) 43.5,-17.12 ; 42.85,-16.47 ccw(c43.5,-16.47) 43.5,-17.12 ; 42.85,-16.47 42.85,-16.1 42.85,-16.47 ; 42.85,-12.82 cw(c43.55,-12.82) 43.55,-12.12 ; 42.85,-12.82 cw(c43.55,-12.82) 43.55,-12.12 ; 42.85,-12.82 42.85,-13.74 42.85,-12.82 ; 42.85,-11.49 ccw(c43.48,-11.49) 43.48,-12.12 ; 42.85,-11.49 ccw(c43.48,-11.49) 43.48,-12.12 ; 42.85,-11.49 42.85,-11.37 ; 42.85,-11.49 42.85,-11.37 ; 43.4,-17.12 ccw(c43.4,-17.67) 42.85,-17.67 cw(c43.4,-17.67) 43.4,-17.12 ; 43.4,-17.12 44.25,-17.12 ; 43.4,-17.12 44.25,-17.12 ; 43.48,-12.12 44.25,-12.12 ; 43.48,-12.12 44.25,-12.12 ; 43.5,-17.12 44.22,-17.12 ; 43.5,-17.12 44.22,-17.12 ; 43.55,-12.12 44.25,-12.12 ; 43.55,-12.12 44.25,-12.12 ; 44.22,-17.12 ccw(c44.22,-16.49) 44.85,-16.49 cw(c44.22,-16.49) 44.22,-17.12 ; 44.25,-17.12 cw(c44.25,-17.72) 44.85,-17.72 ; 44.25,-17.12 cw(c44.25,-17.72) 44.85,-17.72 ; 44.25,-12.12 cw(c44.25,-12.72) 44.85,-12.72 ccw(c44.25,-12.72) 44.25,-12.12 ; 44.25,-12.12 ccw(c44.25,-11.52) 44.85,-11.52 ; 44.25,-12.12 ccw(c44.25,-11.52) 44.85,-11.52 ; 44.85,-17.72 44.85,-11.52 ; 44.85,-17.72 51.35,-17.72 ; 44.85,-17.72 44.85,-11.52 ; 44.85,-17.72 51.35,-17.72 ; 44.85,-11.52 51.35,-11.52 ; 44.85,-11.52 51.35,-11.52 ; 45.53,-17.72 cw(c45.53,-17.04) 44.85,-17.04 ccw(c45.53,-17.04) 45.53,-17.72 ; 45.53,-17.72 45.68,-17.72 45.53,-17.72 ; 50.73,-17.72 ccw(c50.73,-17.1) 51.35,-17.1 cw(c50.73,-17.1) 50.73,-17.72 ; 50.73,-17.72 50.5,-17.72 50.73,-17.72 ; 50.81,-11.52 cw(c50.81,-12.06) 51.35,-12.06 ccw(c50.81,-12.06) 50.81,-11.52 ; 50.81,-11.52 50.41,-11.52 50.81,-11.52 ; 51.35,-17.72 51.35,-11.52 ; 51.35,-17.72 51.35,-11.52 ; 42.68,-17.12 44.85,-17.12 42.68,-17.12 ; 42.85,-12.12 44.85,-12.12 42.85,-12.12 ; 44.85,-12.13 cw(c45.46,-12.13) 45.46,-11.52 ccw(c45.46,-12.13) 44.85,-12.13
  text "E32(915T30D)" at 12.446,-8.763 h2.8
  text "ANT" at 36.83,-15.19 h1.8
  text "M0" at 2.063,-0.54 h1.8
  text "M1" at 2.063,-3.08 h1.8
  text "RXD" at 2.063,-5.62 h1.8
  text "TXD" at 2.063,-8.16 h1.8
  text "AUX" at 2.063,-10.7 h1.8
  text "VCC" at 2.063,-13.24 h1.8
  text "GND" at 2.063,-15.78 h1.8
  text "GND" at 33.426,-5.429 h1.8
  text "GND" at 33.426,-3.016 h1.8
  text "GND" at 33.457,-0.381 h1.8
  text "GND" at 33.457,-8.001 h1.8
